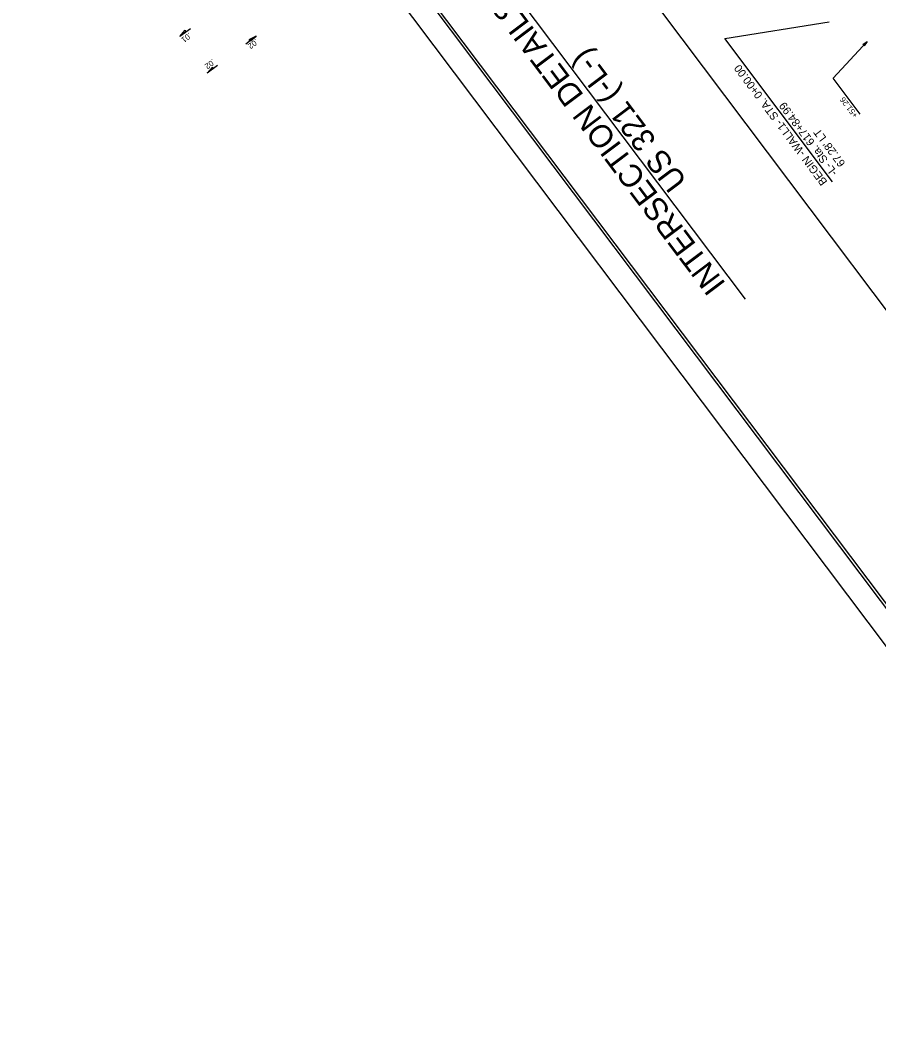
# Model space of a CAD drawing. Extents: x 1263113 to 1265001, y 775064 to 777068.
# Drawn here: x 1263113 to 1263865, y 775064 to 775951 of the extents above; entities that cross this region are included whole.
import ezdxf

# ---------------------------------------------------------------- set-up
doc = ezdxf.new("R2010")
doc.units = 0
for name, color, linetype in [('Prop Dimension', 7, 'Continuous'), ('Prop Dimension Text', 7, 'Continuous'), ('Prop Horizontal Alignment Curve and Spiral Data', 7, 'Continuous'), ('Prop Horizontal Alignment Station Label', 7, 'Continuous'), ('Prop Superelevation  Arrow CELL', 7, 'Continuous'), ('Prop Superelevation Label', 7, 'Continuous'), ('Prop Terminator CELL', 7, 'Continuous'), ('Sheet Plot Border Inside CELL', 7, 'Continuous'), ('Sheet Plot Border Outside CELL', 7, 'Continuous'), ('Sheet Typical CELL', 7, 'Continuous')]:
    doc.layers.add(name, color=color, linetype=linetype)

msp = doc.modelspace()

# ---------------------------------------------------------------- linework, layer by layer
at = {"layer": 'Prop Dimension'}
for p in [(1263854.39, 775932.31), (1263848.33, 775868.84)]:
    msp.add_line(p, (1263824.66, 775900.27), dxfattribs=at)
at = {"layer": 'Prop Horizontal Alignment Curve and Spiral Data'}
msp.add_line((1263747.97, 775706.98), (1263512.82, 776019.17), dxfattribs=at)
at = {"layer": 'Prop Horizontal Alignment Station Label'}
for p, q in [((1263729.95, 775935.01), (1263821.19, 775949.58)), ((1263824.21, 775809.49), (1263729.95, 775935.01))]:
    msp.add_line(p, q, dxfattribs=at)
at = {"layer": 'Prop Superelevation  Arrow CELL'}
for points in [[(1263253.12, 775936.56), (1263257.74, 775942.05), (1263257.83, 775940.11)], [(1263253.12, 775936.56), (1263257.74, 775942.05), (1263257.83, 775940.11)], [(1263319.9, 775936.78), (1263313.34, 775933.85), (1263315.18, 775933.23)], [(1263319.9, 775936.78), (1263313.34, 775933.85), (1263315.18, 775933.23)], [(1263276.96, 775904.44), (1263281.59, 775909.93), (1263281.68, 775907.99)]]:
    msp.add_lwpolyline(points, close=True, dxfattribs=at)
at = {"layer": 'Prop Superelevation Label'}
for p, q in [((1263262.19, 775943.39), (1263253.12, 775936.56)), ((1263319.9, 775936.78), (1263310.82, 775929.95)), ((1263286.04, 775911.28), (1263276.96, 775904.44))]:
    msp.add_line(p, q, dxfattribs=at)
at = {"layer": 'Prop Terminator CELL'}
msp.add_lwpolyline([(1263850.76, 775929.54), (1263854.39, 775932.31), (1263851.9, 775928.45), (1263851.7, 775929.42)], close=True, dxfattribs=at)
at = {"layer": 'Sheet Plot Border Inside CELL'}
msp.add_lwpolyline([(1264977.07, 775721.54), (1263974.73, 777052.27), (1263132.03, 776417.56), (1264134.37, 775086.81)], close=True, dxfattribs=at)
at = {"layer": 'Sheet Plot Border Outside CELL'}
msp.add_lwpolyline([(1263113.35, 776409.12), (1264126.21, 775064.39), (1265000.86, 775723.19), (1263988, 777067.91)], close=True, dxfattribs=at)
at = {"layer": 'Sheet Typical CELL'}
msp.add_line((1264044, 775210.92), (1263141.54, 776409.07), dxfattribs=at)
msp.add_lwpolyline([(1263432.63, 776279.56), (1264082.63, 775416.59), (1264341.8, 775611.8), (1263691.81, 776474.77)], close=True, dxfattribs=at)

# ---------------------------------------------------------------- texts
at = {"layer": 'Prop Dimension Text'}
msp.add_text('+51.26', height=5, rotation=127.72556, dxfattribs=at).set_placement((1263846.73, 775867.92))
at = {"layer": 'Prop Horizontal Alignment Curve and Spiral Data'}
for s, p in [('INTERSECTION DETAILS', (1263731.35, 775720.21)), ('US 321 (-L-)', (1263697.52, 775810.23))]:
    msp.add_text(s, height=20, rotation=126.98742, dxfattribs=at).set_placement(p)
at = {"layer": 'Prop Horizontal Alignment Station Label'}
for s, p in [('BEGIN -WALL1- STA. 0+00.00 ', (1263819.93, 775809.54)), ('-L- Sta. 617+84.99', (1263828.88, 775817.64)), ("67.28' LT", (1263835.74, 775825.77))]:
    msp.add_text(s, height=7, rotation=126.67859, dxfattribs=at).set_placement(p)
at = {"layer": 'Prop Superelevation Label'}
for s, p in [('.01', (1263261.06, 775940.37)), ('.02', (1263319.35, 775934.95)), ('.02', (1263281.67, 775917.28))]:
    msp.add_text(s, height=5, rotation=217.25838, dxfattribs=at).set_placement(p)

doc.saveas('drawing.dxf')
